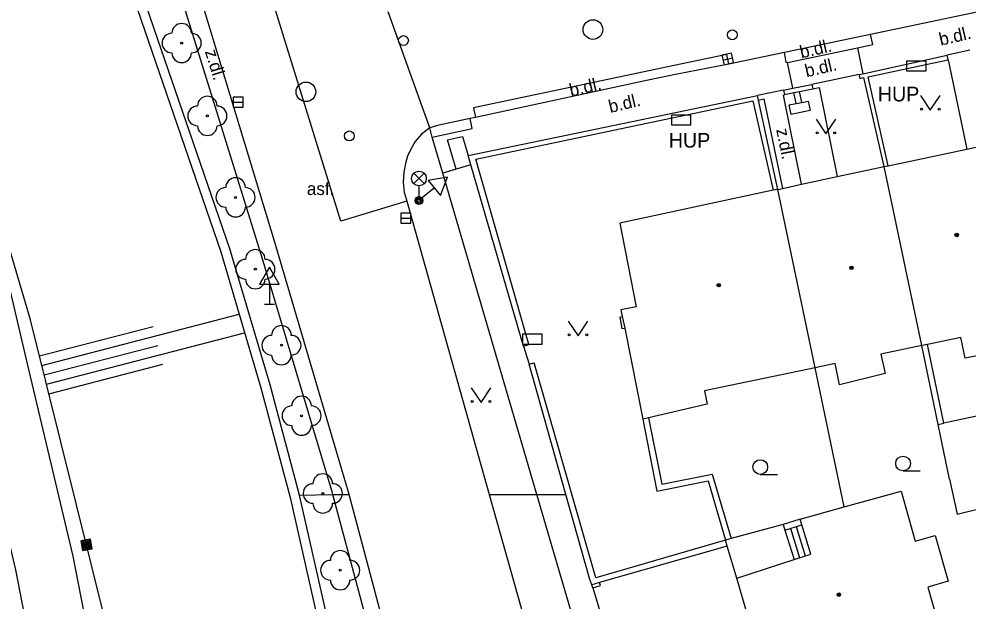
# Model space of a CAD drawing. Extents: x -596229 to -595156, y -1161237 to -1159376.
# Drawn here: x -595936.1 to -595887.66, y -1161054.1 to -1161024.38 of the extents above; entities that cross this region are included whole.
import ezdxf

# ---------------------------------------------------------------- set-up
doc = ezdxf.new("R2010")
doc.units = 0
for name, color, linetype in [('DOP - kresba z DSPS bez souradnic', 7, 'Continuous'), ('DOP - rozhrani ploch obecne', 7, 'Continuous'), ('Level 22', 7, 'Continuous'), ('Level 24', 7, 'Continuous'), ('Level 25', 7, 'Continuous'), ('Level 27', 7, 'Continuous'), ('Level 28', 7, 'Continuous'), ('Level 31', 7, 'Continuous'), ('Level 33', 7, 'Continuous'), ('Level 34', 7, 'Continuous'), ('Level 36', 7, 'Continuous'), ('Level 39', 7, 'Continuous'), ('plynovod - povrch.  znaky - PRIS skut. velikost', 7, 'Continuous'), ('silnoproud - povrch.  znaky a  RIS  skut. velikost', 7, 'Continuous'), ('Specificka linie pasportu komunikaci', 7, 'Continuous'), ('TM - budovy zdene_ betonove - VP', 7, 'Continuous'), ('TM - CD - osa koleji', 7, 'Continuous'), ('TM - chodniky - VP', 7, 'Continuous'), ('TM - horni hrana svahu', 7, 'Continuous'), ('TM - komunikace - VP', 7, 'Continuous'), ('TM - letecke snimky - pomocna linie', 7, 'Continuous'), ('TM - plot drateny_ kovovy - VP', 7, 'Continuous'), ('TM - plot zdeny_ ohradni zed - VP', 7, 'Continuous'), ('TM - podezdivka plotu - VP', 7, 'Continuous'), ('TM - popis objektu', 7, 'Continuous'), ('TM - popis povrchu', 7, 'Continuous'), ('TM - rozhrani ploch obecne - VP', 7, 'Continuous'), ('TM - schody - VP', 7, 'Continuous'), ('TM - srafovani', 7, 'Continuous'), ('TM - vjezd na pozemek', 7, 'Continuous')]:
    doc.layers.add(name, color=color, linetype=linetype)

msp = doc.modelspace()

# ---------------------------------------------------------------- linework, layer by layer
at = {"layer": 'DOP - kresba z DSPS bez souradnic'}
for points in [[(-595888.9, -1161045.02), (-595889.74, -1161041)], [(-595883.87, -1161043.95), (-595888.9, -1161045.02)], [(-595903.97, -1161044.75), (-595903.3, -1161048.13)], [(-595889.19, -1161045.08), (-595888.9, -1161045.02)], [(-595903.3, -1161048.13), (-595900.72, -1161047.62)], [(-595900.72, -1161047.62), (-595899.76, -1161050.91)]]:
    msp.add_lwpolyline(points, dxfattribs=at)
at = {"layer": 'DOP - rozhrani ploch obecne'}
for points in [[(-595889.19, -1161045.08), (-595890.03, -1161041.06)], [(-595893.99, -1161049.3), (-595895.47, -1161042.19)], [(-595904.27, -1161044.82), (-595903.54, -1161048.49)], [(-595888.61, -1161047.88), (-595889.19, -1161045.08)], [(-595903.54, -1161048.49), (-595900.93, -1161047.97)], [(-595900.93, -1161047.97), (-595900.04, -1161050.99)], [(-595888.61, -1161047.88), (-595888.22, -1161049.67)], [(-595888.22, -1161049.67), (-595882.91, -1161048.36)]]:
    msp.add_lwpolyline(points, dxfattribs=at)
at = {"layer": 'Level 22'}
for centre in [(-595927.8, -1161025.61), (-595926.49, -1161029.33), (-595925.05, -1161033.49), (-595924.04, -1161037.16), (-595922.71, -1161041.04), (-595921.68, -1161044.64), (-595920.6, -1161048.61), (-595919.71, -1161052.53)]:
    msp.add_circle(centre, 0.05, dxfattribs=at)
for centre, start, end in [((-595927.8, -1161025.11), 0, 180), ((-595928.3, -1161025.61), 90, 270), ((-595927.3, -1161025.61), 270, 90), ((-595927.8, -1161026.11), 180, 0), ((-595926.49, -1161028.83), 0, 180), ((-595926.99, -1161029.33), 90, 270), ((-595925.99, -1161029.33), 270, 90), ((-595926.49, -1161029.83), 180, 0), ((-595925.05, -1161032.99), 0, 180), ((-595925.55, -1161033.49), 90, 270), ((-595924.55, -1161033.49), 270, 90), ((-595925.05, -1161033.99), 180, 0), ((-595924.04, -1161036.66), 0, 180), ((-595924.54, -1161037.16), 90, 270), ((-595923.54, -1161037.16), 270, 90), ((-595924.04, -1161037.66), 180, 0), ((-595922.71, -1161040.54), 0, 180), ((-595923.21, -1161041.04), 90, 270), ((-595922.21, -1161041.04), 270, 90), ((-595922.71, -1161041.54), 180, 0), ((-595921.68, -1161044.14), 0, 180), ((-595922.18, -1161044.64), 90, 270), ((-595921.18, -1161044.64), 270, 90), ((-595921.68, -1161045.14), 180, 0), ((-595920.6, -1161048.11), 0, 180), ((-595921.1, -1161048.61), 90, 270), ((-595920.1, -1161048.61), 270, 90), ((-595920.6, -1161049.11), 180, 0), ((-595919.71, -1161052.03), 0, 180), ((-595920.21, -1161052.53), 90, 270), ((-595919.21, -1161052.53), 270, 90), ((-595919.71, -1161053.03), 180, 0)]:
    msp.add_arc(centre, 0.5, start, end, dxfattribs=at)
at = {"layer": 'Level 24'}
for points in [[(-595890.808, -1161027.029), (-595889.808, -1161027.029), (-595889.808, -1161026.529), (-595890.808, -1161026.529)], [(-595902.808, -1161029.789), (-595901.808, -1161029.789), (-595901.808, -1161029.289), (-595902.808, -1161029.289)], [(-595910.397, -1161040.978), (-595909.397, -1161040.978), (-595909.397, -1161040.478), (-595910.397, -1161040.478)]]:
    msp.add_lwpolyline(points, close=True, dxfattribs=at)
at = {"layer": 'Level 25'}
for points in [[(-595932.951, -1161051.03), (-595932.86, -1161051.522), (-595932.368, -1161051.43), (-595932.46, -1161050.938)], [(-595932.893, -1161051.07), (-595932.82, -1161051.463), (-595932.427, -1161051.39), (-595932.5, -1161050.997)], [(-595932.835, -1161051.11), (-595932.78, -1161051.405), (-595932.485, -1161051.35), (-595932.54, -1161051.055)], [(-595932.777, -1161051.15), (-595932.74, -1161051.347), (-595932.543, -1161051.31), (-595932.58, -1161051.113)], [(-595932.718, -1161051.19), (-595932.7, -1161051.288), (-595932.602, -1161051.27), (-595932.62, -1161051.172)]]:
    msp.add_lwpolyline(points, close=True, dxfattribs=at)
at = {"layer": 'Level 27'}
for p, q in [((-595900.174, -1161026.476), (-595899.686, -1161026.364)), ((-595925.17, -1161028.63), (-595924.67, -1161028.63)), ((-595916.61, -1161034.55), (-595916.11, -1161034.55))]:
    msp.add_line(p, q, dxfattribs=at)
for points in [[(-595900.117, -1161026.72), (-595899.63, -1161026.607), (-595899.743, -1161026.12), (-595900.23, -1161026.233)], [(-595925.17, -1161028.88), (-595924.67, -1161028.88), (-595924.67, -1161028.38), (-595925.17, -1161028.38)], [(-595916.61, -1161034.8), (-595916.11, -1161034.8), (-595916.11, -1161034.3), (-595916.61, -1161034.3)]]:
    msp.add_lwpolyline(points, close=True, dxfattribs=at)
for centre in [(-595906.81, -1161024.92), (-595921.46, -1161028.1)]:
    msp.add_circle(centre, 0.5, dxfattribs=at)
at = {"layer": 'Level 28'}
for centre in [(-595899.69, -1161025.19), (-595919.24, -1161030.35)]:
    msp.add_circle(centre, 0.25, dxfattribs=at)
at = {"layer": 'Level 31'}
msp.add_circle((-595916.48, -1161025.48), 0.25, dxfattribs=at)
at = {"layer": 'Level 33'}
for p, q in [((-595915.955, -1161032.79), (-595915.425, -1161032.26)), ((-595915.955, -1161032.26), (-595915.425, -1161032.79)), ((-595915.69, -1161032.9), (-595915.69, -1161033.65))]:
    msp.add_line(p, q, dxfattribs=at)
for centre, radius in [((-595915.69, -1161032.525), 0.375), ((-595915.69, -1161033.65), 0.2), ((-595915.69, -1161033.65), 0.145), ((-595915.69, -1161033.65), 0.0876)]:
    msp.add_circle(centre, radius, dxfattribs=at)
at = {"layer": 'Level 34'}
for p, q in [((-595914.899, -1161033.009), (-595915.69, -1161033.65)), ((-595923.32, -1161037.922), (-595923.32, -1161038.94)), ((-595923.57, -1161038.94), (-595923.07, -1161038.94))]:
    msp.add_line(p, q, dxfattribs=at)
for points in [[(-595915.214, -1161032.62), (-595914.584, -1161033.397), (-595914.227, -1161032.463)], [(-595923.82, -1161037.922), (-595922.82, -1161037.922), (-595923.32, -1161037.056)]]:
    msp.add_lwpolyline(points, close=True, dxfattribs=at)
at = {"layer": 'Level 36'}
for p, q in [((-595890.98, -1161047.455), (-595890.105, -1161047.455)), ((-595898.27, -1161047.635), (-595897.395, -1161047.635))]:
    msp.add_line(p, q, dxfattribs=at)
for points in [[(-595890.09, -1161028.28), (-595889.59, -1161029.03), (-595889.09, -1161028.28)], [(-595895.42, -1161029.49), (-595894.92, -1161030.24), (-595894.42, -1161029.49)], [(-595908.07, -1161039.81), (-595907.57, -1161040.56), (-595907.07, -1161039.81)], [(-595913.02, -1161043.22), (-595912.52, -1161043.97), (-595912.02, -1161043.22)]]:
    msp.add_lwpolyline(points, dxfattribs=at)
for centre, radius in [((-595890.04, -1161028.98), 0.05), ((-595889.141, -1161028.98), 0.05), ((-595895.37, -1161030.19), 0.05), ((-595894.471, -1161030.19), 0.05), ((-595908.02, -1161040.51), 0.05), ((-595907.121, -1161040.51), 0.05), ((-595912.97, -1161043.92), 0.05), ((-595912.071, -1161043.92), 0.05), ((-595898.27, -1161047.26), 0.375), ((-595890.98, -1161047.08), 0.375)]:
    msp.add_circle(centre, radius, dxfattribs=at)
at = {"layer": 'Level 39'}
for centre, radius in [((-595888.24, -1161035.41), 0.09), ((-595888.24, -1161035.41), 0.0398), ((-595893.61, -1161037.09), 0.09), ((-595893.61, -1161037.09), 0.0398), ((-595900.39, -1161037.97), 0.09), ((-595900.39, -1161037.97), 0.0398), ((-595894.26, -1161053.78), 0.09), ((-595894.26, -1161053.78), 0.0398)]:
    msp.add_circle(centre, radius, dxfattribs=at)
at = {"layer": 'plynovod - povrch.  znaky - PRIS skut. velikost'}
for points in [[(-595896.43, -1161028.7), (-595896.14, -1161028.64)], [(-595896.14, -1161028.64), (-595895.82, -1161028.57), (-595895.72, -1161029.06)], [(-595895.72, -1161029.06), (-595896.7, -1161029.26), (-595896.8, -1161028.77), (-595896.43, -1161028.7)]]:
    msp.add_lwpolyline(points, dxfattribs=at)
at = {"layer": 'silnoproud - povrch.  znaky a  RIS  skut. velikost'}
for points in [[(-595896.43, -1161028.7), (-595896.56, -1161028.14)], [(-595896.14, -1161028.64), (-595896.27, -1161028.08)], [(-595905.44, -1161039.61), (-595905.31, -1161039.58)], [(-595905.44, -1161039.61), (-595905.33, -1161040.19)], [(-595905.33, -1161040.19), (-595905.19, -1161040.17)]]:
    msp.add_lwpolyline(points, dxfattribs=at)
at = {"layer": 'Specificka linie pasportu komunikaci'}
for points in [[(-595916.31, -1161033.69), (-595919.68, -1161034.7), (-595923.3, -1161022.98), (-595919.94, -1161021.82)], [(-595915.14, -1161029.94), (-595917.26, -1161024.01)], [(-595921.78, -1161048.7), (-595920.09, -1161048.66)], [(-595920.09, -1161048.66), (-595919.26, -1161048.66)], [(-595912.1, -1161048.66), (-595909.68, -1161048.66)], [(-595909.68, -1161048.66), (-595908.19, -1161048.66)]]:
    msp.add_lwpolyline(points, dxfattribs=at)
at = {"layer": 'TM - budovy zdene_ betonove - VP'}
for points in [[(-595891.74, -1161031.88), (-595887.72, -1161031.03)], [(-595887.72, -1161031.03), (-595886.56, -1161030.78)], [(-595894.35, -1161032.43), (-595891.94, -1161031.92)], [(-595891.94, -1161031.92), (-595891.74, -1161031.88)], [(-595890.03, -1161041.06), (-595891.94, -1161031.92)], [(-595896.17, -1161032.82), (-595894.35, -1161032.43)], [(-595897.37, -1161033.08), (-595897.14, -1161033.03)], [(-595897.14, -1161033.03), (-595896.17, -1161032.82)], [(-595897.61, -1161033.13), (-595905.44, -1161034.8)], [(-595897.37, -1161033.08), (-595897.61, -1161033.13)], [(-595895.47, -1161042.19), (-595897.37, -1161033.08)], [(-595905.44, -1161034.8), (-595904.6, -1161039.08)], [(-595904.6, -1161039.08), (-595905.38, -1161039.24)], [(-595905.38, -1161039.24), (-595905.31, -1161039.58)], [(-595905.31, -1161039.58), (-595905.19, -1161040.17)], [(-595905.19, -1161040.17), (-595904.27, -1161044.82)], [(-595888.03, -1161040.64), (-595889.74, -1161041)], [(-595887.81, -1161041.7), (-595888.03, -1161040.64)], [(-595890.03, -1161041.06), (-595892.11, -1161041.49)], [(-595889.74, -1161041), (-595890.03, -1161041.06)], [(-595885.47, -1161041.24), (-595887.81, -1161041.7)], [(-595892.11, -1161041.49), (-595891.9, -1161042.49)], [(-595895.47, -1161042.19), (-595901.12, -1161043.37)], [(-595894.45, -1161041.98), (-595895.47, -1161042.19)], [(-595894.23, -1161043.06), (-595894.45, -1161041.98)], [(-595891.9, -1161042.49), (-595894.23, -1161043.06)], [(-595901.12, -1161043.37), (-595900.98, -1161044.05)], [(-595900.98, -1161044.05), (-595903.97, -1161044.75)], [(-595903.97, -1161044.75), (-595904.27, -1161044.82)], [(-595893.99, -1161049.3), (-595891.08, -1161048.5)], [(-595891.08, -1161048.5), (-595890.36, -1161051.04)], [(-595896.24, -1161049.92), (-595893.99, -1161049.3)], [(-595896.15, -1161050.21), (-595896.24, -1161049.92)], [(-595895.68, -1161051.71), (-595896.15, -1161050.21)], [(-595890.36, -1161051.04), (-595889.35, -1161050.76)], [(-595889.35, -1161050.76), (-595888.67, -1161053.09)], [(-595896.54, -1161051.99), (-595895.68, -1161051.71)], [(-595899.47, -1161052.94), (-595896.54, -1161051.99)], [(-595898.85, -1161055.04), (-595899.47, -1161052.94)], [(-595888.67, -1161053.09), (-595889.71, -1161053.39)], [(-595889.71, -1161053.39), (-595889.11, -1161055.54)]]:
    msp.add_lwpolyline(points, dxfattribs=at)
at = {"layer": 'TM - CD - osa koleji'}
msp.add_lwpolyline([(-595932.77, -1161071.33), (-595933.49, -1161067.01), (-595933.75, -1161065.49), (-595936.27, -1161052.51), (-595940.76, -1161033.53), (-595944.99, -1161018.31), (-595952.18, -1160995.78), (-595964.08, -1160961.74), (-595973.9, -1160934.08), (-595976.55, -1160926.59), (-595979.47, -1160918.46), (-595984.79, -1160903.55)], dxfattribs=at)
at = {"layer": 'TM - chodniky - VP'}
for points in [[(-595898.36, -1161028.53), (-595898.08, -1161028.46)], [(-595898.08, -1161028.46), (-595897.14, -1161033.03)], [(-595896.17, -1161032.82), (-595897.09, -1161028.27), (-595897.04, -1161028.24)], [(-595915.01, -1161030.41), (-595915.14, -1161029.94)], [(-595914.47, -1161032.25), (-595915.01, -1161030.41)], [(-595909.68, -1161048.66), (-595914.47, -1161032.25)], [(-595910.45, -1161054.52), (-595909.13, -1161055.23), (-595907.86, -1161054.87), (-595909.68, -1161048.66)]]:
    msp.add_lwpolyline(points, dxfattribs=at)
at = {"layer": 'TM - horni hrana svahu'}
msp.add_lwpolyline([(-595928.09, -1161069.64), (-595929.3, -1161064.73), (-595935.52, -1161039.74), (-595946.19, -1161003.54), (-595961.27, -1160959.66), (-595971.33, -1160931.82), (-595976.13, -1160918.19), (-595979.12, -1160909.99)], dxfattribs=at)
at = {"layer": 'TM - komunikace - VP'}
for points in [[(-595923.69, -1161036.57), (-595932.45, -1161008.33)], [(-595885.43, -1161023.65), (-595892.64, -1161025.17)], [(-595892.64, -1161025.17), (-595897.04, -1161026.09)], [(-595897.04, -1161026.09), (-595899.88, -1161026.69)], [(-595899.88, -1161026.69), (-595902.51, -1161027.2), (-595904.08, -1161027.52), (-595912.8, -1161029.41)], [(-595913.08, -1161029.47), (-595914.74, -1161029.82), (-595915.14, -1161029.94)], [(-595912.8, -1161029.41), (-595913.08, -1161029.47)], [(-595915.14, -1161029.94), (-595915.56, -1161030.26), (-595915.89, -1161030.64), (-595916.11, -1161031.02), (-595916.28, -1161031.39), (-595916.38, -1161031.76), (-595916.47, -1161032.2), (-595916.5, -1161032.72), (-595916.44, -1161033.23), (-595916.35, -1161033.56), (-595916.31, -1161033.69)], [(-595916.31, -1161033.69), (-595912.1, -1161048.66)], [(-595920.09, -1161048.66), (-595920.12, -1161048.53), (-595923.69, -1161036.57)], [(-595916.8, -1161060.49), (-595917.94, -1161056.66), (-595920.09, -1161048.66)], [(-595912.1, -1161048.66), (-595910.45, -1161054.52)]]:
    msp.add_lwpolyline(points, dxfattribs=at)
at = {"layer": 'TM - letecke snimky - pomocna linie'}
for points in [[(-595888.68, -1161026.47), (-595887.72, -1161031.03)], [(-595895.58, -1161027.94), (-595895.27, -1161027.88), (-595894.35, -1161032.43)], [(-595937.84, -1161032.84), (-595935.68, -1161041.99), (-595933.35, -1161051.82), (-595930.79, -1161064.98), (-595930.53, -1161066.51), (-595929.81, -1161070.84), (-595927.25, -1161086.21), (-595927.21, -1161086.48), (-595925.17, -1161098.79), (-595925.11, -1161099.16), (-595923.98, -1161106.01), (-595919.85, -1161132.8), (-595919.58, -1161134.76), (-595919.53, -1161135.06), (-595918.06, -1161145.53), (-595918.05, -1161145.64), (-595917.54, -1161150.42)]]:
    msp.add_lwpolyline(points, dxfattribs=at)
at = {"layer": 'TM - plot drateny_ kovovy - VP'}
for points in [[(-595891.74, -1161031.88), (-595892.77, -1161027.33), (-595889.82, -1161026.71)], [(-595889.82, -1161026.71), (-595888.68, -1161026.47)], [(-595893.18, -1161027.42), (-595892.98, -1161027.37)], [(-595897.04, -1161028.24), (-595896.56, -1161028.14)], [(-595896.56, -1161028.14), (-595896.27, -1161028.08)], [(-595896.27, -1161028.08), (-595895.58, -1161027.94)], [(-595912.79, -1161031.54), (-595902.85, -1161029.45), (-595901.87, -1161029.24), (-595898.64, -1161028.56), (-595897.61, -1161033.13)], [(-595910.08, -1161041.01), (-595910.1, -1161040.94), (-595910.18, -1161040.65), (-595912.79, -1161031.54)], [(-595910.35, -1161041.09), (-595910.08, -1161041.01)], [(-595910.07, -1161042.01), (-595909.81, -1161041.94)], [(-595906.67, -1161052.92), (-595909.81, -1161041.94)], [(-595897.1, -1161050.19), (-595899.76, -1161050.91)], [(-595897.1, -1161050.19), (-595897.01, -1161050.48)], [(-595897.01, -1161050.48), (-595896.15, -1161050.21)], [(-595899.76, -1161050.91), (-595900.04, -1161050.99)], [(-595900.04, -1161050.99), (-595906.67, -1161052.92)], [(-595906.42, -1161053.31), (-595906.47, -1161053.15)]]:
    msp.add_lwpolyline(points, dxfattribs=at)
at = {"layer": 'TM - plot zdeny_ ohradni zed - VP'}
for points in [[(-595936.62, -1161005.41), (-595933.02, -1161015.27), (-595925.81, -1161036.27)], [(-595925.81, -1161036.27), (-595923.76, -1161043.21)], [(-595923.76, -1161043.21), (-595922.27, -1161048.82)], [(-595922.27, -1161048.82), (-595919.33, -1161061.8), (-595918.84, -1161061.69)]]:
    msp.add_lwpolyline(points, dxfattribs=at)
at = {"layer": 'TM - podezdivka plotu - VP'}
for points in [[(-595893.03, -1161027.18), (-595888.73, -1161026.23)], [(-595888.68, -1161026.47), (-595888.73, -1161026.23)], [(-595893.22, -1161027.22), (-595893.03, -1161027.18)], [(-595893.22, -1161027.22), (-595893.18, -1161027.42)], [(-595891.94, -1161031.92), (-595892.98, -1161027.37)], [(-595897.09, -1161028.01), (-595896.61, -1161027.92)], [(-595897.09, -1161028.01), (-595897.04, -1161028.24)], [(-595896.61, -1161027.92), (-595895.63, -1161027.72)], [(-595895.63, -1161027.72), (-595895.58, -1161027.94)], [(-595913.18, -1161031.36), (-595898.41, -1161028.29)], [(-595898.36, -1161028.53), (-595898.41, -1161028.29)], [(-595897.37, -1161033.08), (-595898.36, -1161028.53)], [(-595913.04, -1161031.83), (-595913.18, -1161031.36)], [(-595910.35, -1161041.09), (-595913.04, -1161031.83)], [(-595908.19, -1161048.66), (-595910.07, -1161042.01)], [(-595906.96, -1161053), (-595908.19, -1161048.66)], [(-595896.24, -1161049.92), (-595897.1, -1161050.19)], [(-595899.95, -1161051.3), (-595906.47, -1161053.15)], [(-595899.95, -1161051.3), (-595900.04, -1161050.99)], [(-595906.87, -1161053.27), (-595906.96, -1161053)], [(-595906.47, -1161053.15), (-595906.87, -1161053.27)], [(-595906.82, -1161053.43), (-595906.87, -1161053.27)], [(-595906.82, -1161053.43), (-595906.42, -1161053.31)]]:
    msp.add_lwpolyline(points, dxfattribs=at)
at = {"layer": 'TM - rozhrani ploch obecne - VP'}
for points in [[(-595919.34, -1161048.37), (-595923.06, -1161035.72), (-595927.39, -1161021.46), (-595931.25, -1161009.98), (-595931.85, -1161008.07)], [(-595925.34, -1161036.11), (-595932.55, -1161015.11)], [(-595893.31, -1161025.85), (-595892.53, -1161025.68), (-595892.64, -1161025.17)], [(-595899.88, -1161026.69), (-595899.98, -1161026.2), (-595902.34, -1161026.69), (-595912.9, -1161028.92), (-595912.8, -1161029.41)], [(-595896.88, -1161026.6), (-595896.94, -1161026.6), (-595897.04, -1161026.09)], [(-595896.88, -1161026.6), (-595893.31, -1161025.85)], [(-595893.31, -1161025.85), (-595893.03, -1161027.18)], [(-595896.61, -1161027.92), (-595896.88, -1161026.6)], [(-595915.01, -1161030.41), (-595912.97, -1161029.98), (-595913.08, -1161029.47)], [(-595913.79, -1161032.05), (-595914.23, -1161030.56), (-595913.46, -1161030.39), (-595913.18, -1161031.36)], [(-595913.79, -1161032.05), (-595914.47, -1161032.25)], [(-595913.04, -1161031.83), (-595913.79, -1161032.05)], [(-595923.28, -1161043.07), (-595925.34, -1161036.11)], [(-595921.78, -1161048.7), (-595923.28, -1161043.07)], [(-595919.26, -1161048.66), (-595919.34, -1161048.37)], [(-595918.84, -1161061.69), (-595921.78, -1161048.7)], [(-595916.18, -1161059.99), (-595917.14, -1161056.59), (-595919.26, -1161048.66)], [(-595897.01, -1161050.48), (-595896.54, -1161051.99)], [(-595899.47, -1161052.94), (-595899.95, -1161051.3)]]:
    msp.add_lwpolyline(points, dxfattribs=at)
at = {"layer": 'TM - schody - VP'}
for points in [[(-595896.72, -1161050.39), (-595896.26, -1161051.9)], [(-595896.44, -1161050.3), (-595895.97, -1161051.8)]]:
    msp.add_lwpolyline(points, dxfattribs=at)
at = {"layer": 'TM - srafovani'}
for points in [[(-595934.94, -1161042.07), (-595924.87, -1161039.45)], [(-595935.06, -1161041.58), (-595929.26, -1161040.08)], [(-595934.7, -1161043.03), (-595924.59, -1161040.41)], [(-595934.82, -1161042.55), (-595929.01, -1161041.05)], [(-595934.58, -1161043.52), (-595928.76, -1161042.01)]]:
    msp.add_lwpolyline(points, dxfattribs=at)
at = {"layer": 'TM - vjezd na pozemek'}
for points in [[(-595887.57, -1161025.97), (-595888.73, -1161026.23)], [(-595893.22, -1161027.22), (-595895.63, -1161027.72)], [(-595897.09, -1161028.01), (-595898.41, -1161028.29)], [(-595910.35, -1161041.09), (-595910.07, -1161042.01)], [(-595906.82, -1161053.43), (-595905.72, -1161057.06)]]:
    msp.add_lwpolyline(points, dxfattribs=at)

# ---------------------------------------------------------------- texts
at = {"layer": 'TM - popis objektu'}
for p in [(-595892.27, -1161028.59), (-595902.94, -1161030.95)]:
    msp.add_text('HUP', height=0.75, dxfattribs=at).set_placement(p)
at = {"layer": 'TM - popis povrchu'}
for s, rotation, p in [('b.dl.', 13.11, (-595889.06, -1161025.75)), ('b.dl.', 13.11, (-595896.17, -1161026.4)), ('z.dl.', 287.06, (-595926.62, -1161026.04)), ('b.dl.', 13.11, (-595895.91, -1161027.36)), ('b.dl.', 13.11, (-595907.93, -1161028.35)), ('b.dl.', 13.11, (-595905.93, -1161029.18)), ('z.dl.', 281.4519, (-595897.46, -1161030.03))]:
    msp.add_text(s, height=0.65, rotation=rotation, dxfattribs=at).set_placement(p)
msp.add_text('asf.', height=0.65, dxfattribs=at).set_placement((-595921.41, -1161033.37))

doc.saveas('drawing.dxf')
